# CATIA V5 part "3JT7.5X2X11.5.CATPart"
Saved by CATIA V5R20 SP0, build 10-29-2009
Part number: 3JT7.5X2X11.5
Revision: ANY
Definition: UNKNOWN
Nomenclature: 3JT7.5X2X11.5
Source: Unknown
Bounding box of the stored display mesh (mm): x -5.75 to 5.75, y -5.75 to 5.75, z -1 to 1
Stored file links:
  C:\Users\Utente\Desktop\IO LAVORO\3D X SITO CF\CUMSA\3D files PW\pw060622\pw060622_ejection\3JT7.5X2X11.5.CATPart
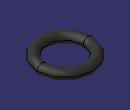
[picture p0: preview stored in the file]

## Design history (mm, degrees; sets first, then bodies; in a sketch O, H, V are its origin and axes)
Body1 "Revolución1" (main body)
  Solid1: solid without history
